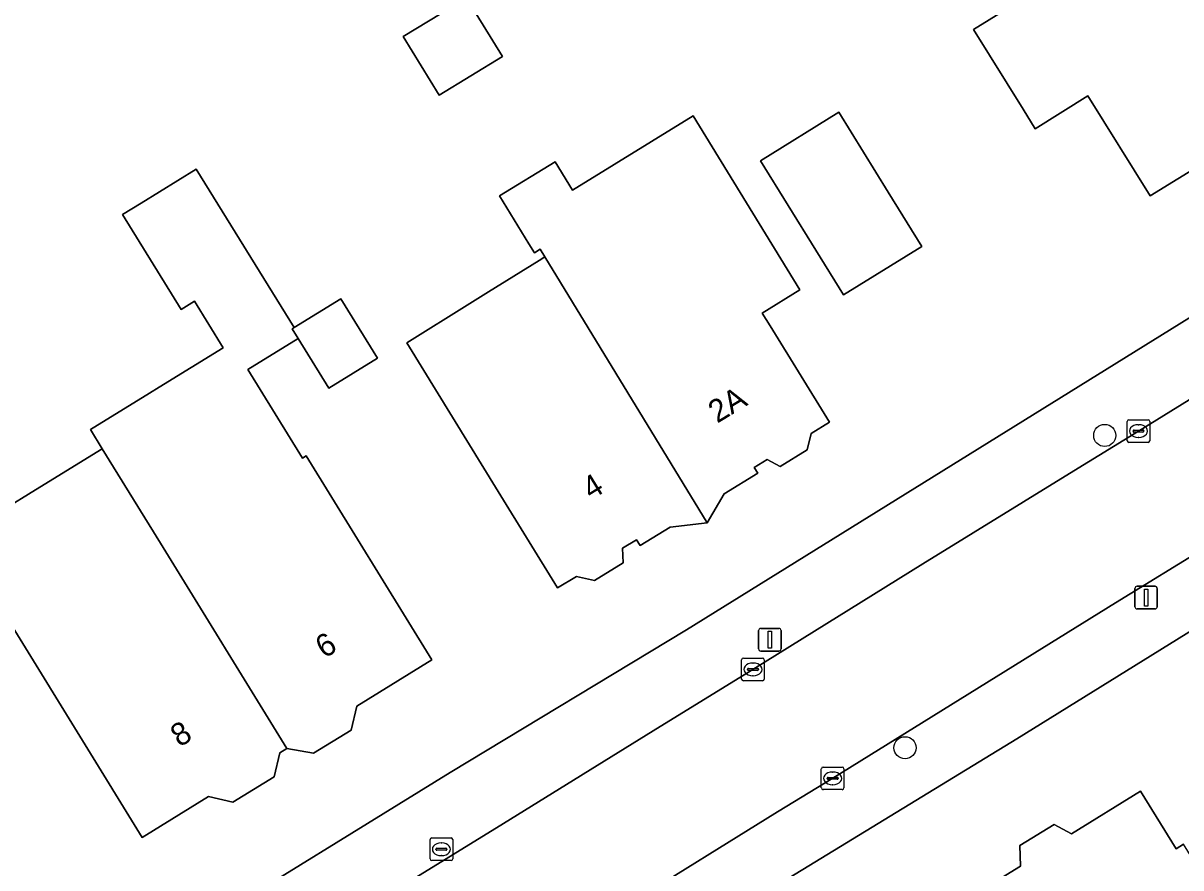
# Model space of a CAD drawing. Extents: x 161347 to 161881, y 382161 to 382804.
# Drawn here: x 161549.1 to 161600.2, y 382361.8 to 382399.1 of the extents above; entities that cross this region are included whole.
import ezdxf

# ---------------------------------------------------------------- set-up
doc = ezdxf.new("R2010")
doc.units = 0
for name, color, linetype in [('IMGEO_Boom', 7, 'Continuous'), ('IMGEO_Brandkraan', 7, 'Continuous'), ('IMGEO_Erf', 7, 'Continuous'), ('IMGEO_Kolk', 7, 'Continuous'), ('IMGEO_Lichtmast', 7, 'Continuous'), ('IMGEO_Pand', 7, 'Continuous'), ('IMGEO_Pand_nummerreeks', 7, 'Continuous'), ('IMGEO_Rijbaan_lokaal_open', 7, 'Continuous'), ('IMGEO_Voetpad_open', 7, 'Continuous')]:
    doc.layers.add(name, color=color, linetype=linetype)

msp = doc.modelspace()

# ---------------------------------------------------------------- linework, layer by layer
at = {"layer": 'IMGEO_Boom'}
for centre in [(161596.861, 382380.871), (161588.036, 382367.068)]:
    msp.add_circle(centre, 0.489, dxfattribs=at)
at = {"layer": 'IMGEO_Brandkraan'}
for p, q in [((161567.047, 382362.157), (161567.047, 382363.009)), ((161567.122, 382363.083), (161567.974, 382363.083)), ((161568.048, 382363.009), (161568.048, 382362.157)), ((161567.306, 382362.577), (161567.306, 382362.589)), ((161567.744, 382362.54), (161567.346, 382362.54)), ((161567.349, 382362.626), (161567.747, 382362.626)), ((161567.535, 382362.863), (161567.56, 382362.863)), ((161567.79, 382362.589), (161567.79, 382362.577)), ((161567.974, 382362.083), (161567.122, 382362.083)), ((161567.558, 382362.303), (161567.533, 382362.303))]:
    msp.add_line(p, q, dxfattribs=at)
for points in [[(161567.047, 382362.157), (161567.047, 382363.009)], [(161567.122, 382363.083), (161567.974, 382363.083)], [(161568.048, 382363.009), (161568.048, 382362.157)], [(161567.974, 382362.083), (161567.122, 382362.083)]]:
    msp.add_lwpolyline(points, dxfattribs=at)
for centre, radius, start, end in [((161567.124, 382363.007), 0.0765, 91.552, 178.448), ((161567.124, 382363.007), 0.0765, 91.552, 178.448), ((161567.972, 382363.007), 0.0765, 1.552, 88.448), ((161567.972, 382363.007), 0.0765, 1.552, 88.448), ((161567.346, 382362.586), 0.0403, 85.8775, 175.7526), ((161567.343, 382362.576), 0.0366, 178.938, 274.7102), ((161567.747, 382362.583), 0.043, 264.8664, 352.4533), ((161567.751, 382362.588), 0.0386, 1.7309, 96.639), ((161567.124, 382362.159), 0.0765, 181.552, 268.448), ((161567.124, 382362.159), 0.0765, 181.552, 268.448), ((161567.972, 382362.159), 0.0765, 271.552, 358.448), ((161567.972, 382362.159), 0.0765, 271.552, 358.448)]:
    msp.add_arc(centre, radius, start, end, dxfattribs=at)
for centre, major_axis, ratio, start_param, end_param in [((161567.534, 382362.583), (-0.387, 0.002), 0.722429, 4.712389, 7.853982), ((161567.559, 382362.583), (-0.39, 0.002), 0.717154, 1.570796, 4.712389)]:
    msp.add_ellipse(centre, major_axis=major_axis, ratio=ratio, start_param=start_param, end_param=end_param, dxfattribs=at)
at = {"layer": 'IMGEO_Erf'}
for points in [[(161604.784, 382395.105), (161598.864, 382391.464), (161596.11, 382395.885), (161593.788, 382394.431), (161593.254, 382395.293), (161591.067, 382398.82), (161592.949, 382399.977), (161589.273, 382405.913), (161588.174, 382405.232), (161582.631, 382414.18), (161587.516, 382417.205), (161590.899, 382411.741), (161593.475, 382413.355), (161592.936, 382414.216), (161595.867, 382416.051), (161596.458, 382415.108), (161600.042, 382417.352), (161600.512, 382416.603)], [(161492.761, 382318.284), (161495.67, 382317.265), (161500, 382320.746), (161506.91, 382326.302), (161519.365, 382335.787), (161532.97, 382344.41), (161567.929, 382365.979), (161578.374, 382372.283), (161617.144, 382396.335)], [(161622.482, 382385.769), (161592.982, 382367.466), (161570.924, 382353.999), (161525.486, 382325.795), (161515.87, 382318.353), (161502.943, 382308.001)], [(161592.301, 382361.316), (161593.136, 382361.832), (161593.108, 382362.748), (161594.62, 382363.681), (161595.388, 382363.268), (161598.437, 382365.151), (161600.014, 382362.599), (161600.346, 382362.804)]]:
    msp.add_lwpolyline(points, dxfattribs=at)
for points in [[(161565.86, 382398.506), (161568.659, 382400.219), (161570.249, 382397.622), (161567.45, 382395.908)], [(161581.645, 382393.017), (161585.108, 382395.155), (161587.292, 382391.62), (161588.771, 382389.226), (161585.309, 382387.087)], [(161571.863, 382388.605), (161572.123, 382388.767), (161571.916, 382389.106), (161571.654, 382388.945), (161571.41, 382389.345), (161570.117, 382391.468), (161572.575, 382392.973), (161573.347, 382391.715), (161578.668, 382394.995), (161583.383, 382387.315), (161581.726, 382386.275), (161582.071, 382385.714), (161584.693, 382381.456), (161583.89, 382380.962), (161583.717, 382380.233), (161582.517, 382379.494), (161581.943, 382379.804), (161581.374, 382379.454), (161581.525, 382379.209), (161580.036, 382378.292), (161579.293, 382377.012), (161577.649, 382376.822), (161576.327, 382376.008), (161576.169, 382376.265), (161575.557, 382375.888), (161575.575, 382375.237), (161574.306, 382374.455), (161573.512, 382374.644), (161572.68, 382374.132), (161570.058, 382378.39), (161566.021, 382384.963), (161568.809, 382386.701), (161569.633, 382387.215)], [(161552.559, 382380.284), (161552.034, 382381.136), (161554.643, 382382.742), (161555.082, 382383.012), (161557.903, 382384.749), (161556.634, 382386.81), (161556.043, 382386.446), (161553.46, 382390.639), (161554.275, 382391.141), (161556.705, 382392.638), (161561.043, 382385.642), (161563.11, 382386.913), (161564.723, 382384.29), (161562.568, 382382.965), (161561.221, 382385.156), (161558.997, 382383.786), (161561.406, 382379.875), (161561.571, 382379.977), (161567.129, 382370.951), (161563.808, 382368.906), (161563.556, 382367.85), (161561.888, 382366.823), (161560.716, 382367.043), (161560.405, 382366.852), (161560.151, 382365.784), (161558.326, 382364.66), (161557.257, 382364.915), (161554.319, 382363.106), (161546.166, 382376.347), (161549.798, 382378.584)]]:
    msp.add_lwpolyline(points, close=True, dxfattribs=at)
at = {"layer": 'IMGEO_Kolk'}
for p, q in [((161597.851, 382380.64), (161597.851, 382381.492)), ((161597.926, 382381.566), (161598.778, 382381.566)), ((161598.339, 382381.346), (161598.364, 382381.346)), ((161598.852, 382381.492), (161598.852, 382380.64)), ((161598.11, 382381.06), (161598.11, 382381.072)), ((161598.548, 382381.023), (161598.15, 382381.023)), ((161598.153, 382381.109), (161598.551, 382381.109)), ((161598.594, 382381.072), (161598.594, 382381.06)), ((161598.778, 382380.566), (161597.926, 382380.566)), ((161598.362, 382380.786), (161598.337, 382380.786)), ((161580.815, 382370.107), (161580.815, 382370.959)), ((161580.89, 382371.033), (161581.742, 382371.033)), ((161581.303, 382370.813), (161581.328, 382370.813)), ((161581.816, 382370.959), (161581.816, 382370.107)), ((161581.074, 382370.527), (161581.074, 382370.539)), ((161581.512, 382370.49), (161581.114, 382370.49)), ((161581.117, 382370.576), (161581.515, 382370.576)), ((161581.326, 382370.253), (161581.301, 382370.253)), ((161581.558, 382370.539), (161581.558, 382370.527)), ((161581.742, 382370.033), (161580.89, 382370.033)), ((161584.336, 382365.291), (161584.336, 382366.143)), ((161584.411, 382366.217), (161585.263, 382366.217)), ((161584.824, 382365.997), (161584.849, 382365.997)), ((161585.337, 382366.143), (161585.337, 382365.291)), ((161584.595, 382365.711), (161584.595, 382365.723)), ((161585.033, 382365.674), (161584.635, 382365.674)), ((161584.638, 382365.76), (161585.036, 382365.76)), ((161585.079, 382365.723), (161585.079, 382365.711)), ((161585.263, 382365.217), (161584.411, 382365.217)), ((161584.847, 382365.437), (161584.822, 382365.437))]:
    msp.add_line(p, q, dxfattribs=at)
for points in [[(161597.851, 382380.64), (161597.851, 382381.492)], [(161597.926, 382381.566), (161598.778, 382381.566)], [(161598.852, 382381.492), (161598.852, 382380.64)], [(161598.778, 382380.566), (161597.926, 382380.566)], [(161580.815, 382370.107), (161580.815, 382370.959)], [(161580.89, 382371.033), (161581.742, 382371.033)], [(161581.816, 382370.959), (161581.816, 382370.107)], [(161581.742, 382370.033), (161580.89, 382370.033)], [(161584.336, 382365.291), (161584.336, 382366.143)], [(161584.411, 382366.217), (161585.263, 382366.217)], [(161585.337, 382366.143), (161585.337, 382365.291)], [(161585.263, 382365.217), (161584.411, 382365.217)]]:
    msp.add_lwpolyline(points, dxfattribs=at)
for centre, radius, start, end in [((161597.928, 382381.49), 0.0765, 91.552, 178.448), ((161597.928, 382381.49), 0.0765, 91.552, 178.448), ((161598.776, 382381.49), 0.0765, 1.552, 88.448), ((161598.776, 382381.49), 0.0765, 1.552, 88.448), ((161598.15, 382381.069), 0.0403, 85.8775, 175.7526), ((161598.147, 382381.059), 0.0366, 178.938, 274.7102), ((161598.551, 382381.066), 0.043, 264.8664, 352.4533), ((161598.555, 382381.071), 0.0386, 1.7309, 96.639), ((161597.928, 382380.642), 0.0765, 181.552, 268.448), ((161597.928, 382380.642), 0.0765, 181.552, 268.448), ((161598.776, 382380.642), 0.0765, 271.552, 358.448), ((161598.776, 382380.642), 0.0765, 271.552, 358.448), ((161580.892, 382370.957), 0.0765, 91.552, 178.448), ((161580.892, 382370.957), 0.0765, 91.552, 178.448), ((161581.74, 382370.957), 0.0765, 1.552, 88.448), ((161581.74, 382370.957), 0.0765, 1.552, 88.448), ((161580.892, 382370.109), 0.0765, 181.552, 268.448), ((161580.892, 382370.109), 0.0765, 181.552, 268.448), ((161581.114, 382370.536), 0.0403, 85.8775, 175.7526), ((161581.111, 382370.526), 0.0366, 178.938, 274.7102), ((161581.515, 382370.533), 0.043, 264.8664, 352.4533), ((161581.519, 382370.538), 0.0386, 1.7309, 96.639), ((161581.74, 382370.109), 0.0765, 271.552, 358.448), ((161581.74, 382370.109), 0.0765, 271.552, 358.448), ((161584.413, 382366.141), 0.0765, 91.552, 178.448), ((161584.413, 382366.141), 0.0765, 91.552, 178.448), ((161585.261, 382366.141), 0.0765, 1.552, 88.448), ((161585.261, 382366.141), 0.0765, 1.552, 88.448), ((161584.635, 382365.72), 0.0403, 85.8775, 175.7526), ((161584.632, 382365.71), 0.0366, 178.938, 274.7102), ((161585.036, 382365.717), 0.043, 264.8664, 352.4533), ((161585.04, 382365.722), 0.0386, 1.7309, 96.639), ((161584.413, 382365.293), 0.0765, 181.552, 268.448), ((161584.413, 382365.293), 0.0765, 181.552, 268.448), ((161585.261, 382365.293), 0.0765, 271.552, 358.448), ((161585.261, 382365.293), 0.0765, 271.552, 358.448)]:
    msp.add_arc(centre, radius, start, end, dxfattribs=at)
for centre, major_axis, ratio, start_param, end_param in [((161598.338, 382381.066), (-0.387, 0.002), 0.722429, 4.712389, 7.853982), ((161598.363, 382381.066), (-0.39, 0.002), 0.717154, 1.570796, 4.712389), ((161581.302, 382370.533), (-0.387, 0.002), 0.722429, 4.712389, 7.853982), ((161581.327, 382370.533), (-0.39, 0.002), 0.717154, 1.570796, 4.712389), ((161584.823, 382365.717), (-0.387, 0.002), 0.722429, 4.712389, 7.853982), ((161584.848, 382365.717), (-0.39, 0.002), 0.717154, 1.570796, 4.712389)]:
    msp.add_ellipse(centre, major_axis=major_axis, ratio=ratio, start_param=start_param, end_param=end_param, dxfattribs=at)
at = {"layer": 'IMGEO_Lichtmast'}
for p, q in [((161598.292, 382374.204), (161599.082, 382374.204)), ((161599.082, 382374.204), (161598.292, 382374.204)), ((161598.192, 382373.304), (161598.192, 382374.104)), ((161598.192, 382374.104), (161598.192, 382373.304)), ((161599.182, 382374.104), (161599.182, 382373.304)), ((161599.182, 382373.304), (161599.182, 382374.104)), ((161599.082, 382373.204), (161598.292, 382373.204)), ((161598.292, 382373.204), (161599.082, 382373.204)), ((161581.564, 382371.445), (161581.564, 382372.245)), ((161581.564, 382372.245), (161581.564, 382371.445)), ((161581.664, 382372.345), (161582.454, 382372.345)), ((161582.454, 382372.345), (161581.664, 382372.345)), ((161582.554, 382372.245), (161582.554, 382371.445)), ((161582.554, 382371.445), (161582.554, 382372.245)), ((161582.454, 382371.345), (161581.664, 382371.345)), ((161581.664, 382371.345), (161582.454, 382371.345))]:
    msp.add_line(p, q, dxfattribs=at)
for points in [[(161598.612, 382374.079), (161598.762, 382374.079), (161598.762, 382373.329), (161598.612, 382373.329), (161598.612, 382374.079)], [(161581.984, 382372.22), (161582.134, 382372.22), (161582.134, 382371.47), (161581.984, 382371.47), (161581.984, 382372.22)]]:
    msp.add_lwpolyline(points, dxfattribs=at)
for centre, start, end in [((161598.292, 382374.104), 90, 180), ((161598.292, 382374.104), 90, 180), ((161599.082, 382374.104), 0, 90), ((161599.082, 382374.104), 360, 90), ((161598.292, 382373.304), 180, 270), ((161598.292, 382373.304), 180, 270), ((161599.082, 382373.304), 270, 0), ((161599.082, 382373.304), 270, 0), ((161581.664, 382372.245), 90, 180), ((161581.664, 382372.245), 90, 180), ((161582.454, 382372.245), 0, 90), ((161582.454, 382372.245), 360, 90), ((161581.664, 382371.445), 180, 270), ((161581.664, 382371.445), 180, 270), ((161582.454, 382371.445), 270, 0), ((161582.454, 382371.445), 270, 0)]:
    msp.add_arc(centre, 0.1, start, end, dxfattribs=at)
at = {"layer": 'IMGEO_Pand'}
for points in [[(161605.788, 382408.1), (161592.949, 382399.977), (161591.067, 382398.82), (161593.254, 382395.293), (161593.788, 382394.431), (161596.11, 382395.885), (161598.864, 382391.464), (161604.784, 382395.105), (161605.156, 382394.512), (161607.703, 382396.106), (161607.282, 382396.777), (161607.874, 382397.148), (161608.803, 382397.181), (161610.248, 382398.086), (161610.406, 382398.773), (161611.333, 382399.354), (161610.602, 382400.523), (161610.764, 382401.23), (161609.674, 382402.97), (161608.887, 382403.152)], [(161565.86, 382398.506), (161567.45, 382395.908), (161570.249, 382397.622), (161568.659, 382400.219)], [(161585.309, 382387.087), (161588.771, 382389.226), (161587.292, 382391.62), (161585.108, 382395.155), (161581.645, 382393.017)], [(161583.383, 382387.315), (161578.668, 382394.995), (161573.347, 382391.715), (161572.575, 382392.973), (161570.117, 382391.468), (161571.41, 382389.345), (161571.654, 382388.945), (161571.916, 382389.106), (161572.123, 382388.767), (161578.926, 382377.608), (161579.293, 382377.012), (161580.036, 382378.292), (161581.525, 382379.209), (161581.374, 382379.454), (161581.943, 382379.804), (161582.517, 382379.494), (161583.717, 382380.233), (161583.89, 382380.962), (161584.693, 382381.456), (161582.071, 382385.714), (161581.726, 382386.275)], [(161561.221, 382385.156), (161560.955, 382385.588), (161561.043, 382385.642), (161556.705, 382392.638), (161554.275, 382391.141), (161553.46, 382390.639), (161556.043, 382386.446), (161556.634, 382386.81), (161557.903, 382384.749), (161555.082, 382383.012), (161554.643, 382382.742), (161552.034, 382381.136), (161552.559, 382380.284), (161555.13, 382376.11), (161560.716, 382367.043), (161561.888, 382366.823), (161563.556, 382367.85), (161563.808, 382368.906), (161567.129, 382370.951), (161561.571, 382379.977), (161561.406, 382379.875), (161558.997, 382383.786)], [(161572.123, 382388.767), (161571.863, 382388.605), (161569.633, 382387.215), (161568.809, 382386.701), (161566.021, 382384.963), (161570.058, 382378.39), (161572.68, 382374.132), (161573.512, 382374.644), (161574.306, 382374.455), (161575.575, 382375.237), (161575.557, 382375.888), (161576.169, 382376.265), (161576.327, 382376.008), (161577.649, 382376.822), (161579.293, 382377.012), (161578.926, 382377.608)], [(161561.221, 382385.156), (161562.568, 382382.965), (161564.723, 382384.29), (161563.11, 382386.913), (161561.043, 382385.642), (161560.955, 382385.588)], [(161560.716, 382367.043), (161555.13, 382376.11), (161552.559, 382380.284), (161549.798, 382378.584), (161546.166, 382376.347), (161554.319, 382363.106), (161557.257, 382364.915), (161558.326, 382364.66), (161560.151, 382365.784), (161560.405, 382366.852)], [(161607.679, 382356.647), (161607.781, 382356.713), (161606.924, 382358.134), (161605.705, 382360.108), (161605.123, 382361.05), (161602.448, 382359.401), (161600.346, 382362.804), (161600.014, 382362.599), (161598.437, 382365.151), (161595.388, 382363.268), (161594.62, 382363.681), (161593.108, 382362.748), (161593.136, 382361.832), (161592.301, 382361.316), (161599.308, 382350.054), (161604.616, 382353.083), (161604.397, 382353.437), (161605.043, 382353.836), (161607.478, 382349.895), (161607.218, 382349.735), (161609.792, 382345.57), (161613.216, 382347.686), (161609.109, 382354.333)]]:
    msp.add_lwpolyline(points, close=True, dxfattribs=at)
at = {"layer": 'IMGEO_Rijbaan_lokaal_open'}
msp.add_lwpolyline([(161563.07, 382352.279), (161575.759, 382360.113), (161582.402, 382364.234), (161584.84, 382365.72), (161594.082, 382371.461), (161597.335, 382373.472), (161601.422, 382375.975), (161609.313, 382380.856), (161606.195, 382385.906), (161598.349, 382381.063), (161595.489, 382379.316), (161588.821, 382375.192), (161581.313, 382370.53), (161577.21, 382368.009), (161570.286, 382363.724), (161563.81, 382359.731), (161558.736, 382356.63), (161552.51, 382352.791), (161555.662, 382347.771), (161557.478, 382348.912)], close=True, dxfattribs=at)
at = {"layer": 'IMGEO_Voetpad_open'}
for points in [[(161588.821, 382375.192), (161595.489, 382379.316), (161598.349, 382381.063), (161606.195, 382385.906), (161608.544, 382387.356), (161617.711, 382393.014), (161617.891, 382393.131), (161617.144, 382396.335), (161578.374, 382372.283), (161567.929, 382365.979), (161532.97, 382344.41), (161519.365, 382335.787), (161506.91, 382326.302), (161500, 382320.746), (161495.67, 382317.265), (161490.849, 382315.425), (161491.37, 382314.562)], [(161570.924, 382353.999), (161592.982, 382367.466), (161622.482, 382385.769), (161620.875, 382387.995), (161620.649, 382387.867), (161611.66, 382382.307), (161609.313, 382380.856), (161601.422, 382375.975), (161597.335, 382373.472), (161594.082, 382371.461), (161584.84, 382365.72), (161582.402, 382364.234), (161575.759, 382360.113), (161563.07, 382352.279), (161557.478, 382348.912), (161555.662, 382347.771), (161553.326, 382346.303), (161546.562, 382342.054), (161540.031, 382338.038), (161533.292, 382333.868), (161527.695, 382330.423)], [(161522.13, 382334.077), (161529.654, 382338.671), (161533.737, 382341.207), (161541.227, 382345.802), (161546.313, 382348.96), (161550.162, 382351.34), (161552.057, 382352.512), (161552.51, 382352.791), (161558.736, 382356.63), (161563.81, 382359.731), (161570.286, 382363.724), (161577.21, 382368.009), (161581.313, 382370.53), (161588.821, 382375.192)]]:
    msp.add_lwpolyline(points, dxfattribs=at)

# ---------------------------------------------------------------- texts
at = {"layer": 'IMGEO_Pand_nummerreeks'}
for s, rotation, p in [('2A', 31.3179, (161579.737, 382381.391)), ('4', 31.6101, (161574.167, 382378.005)), ('6', 31.484, (161562.376, 382370.995)), ('8', 31.4838, (161555.974, 382367.074))]:
    msp.add_text(s, height=1, rotation=rotation, dxfattribs=at).set_placement(p)

doc.saveas('drawing.dxf')
